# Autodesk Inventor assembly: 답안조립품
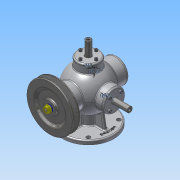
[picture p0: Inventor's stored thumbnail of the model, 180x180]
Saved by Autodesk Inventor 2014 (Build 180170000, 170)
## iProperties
Created: 2016-01
Part Number: 답안조립품
Document SubType Name: Assembly
Designer: Administrator
Mass: 3770.67 g
Surface Area: 2410.99 cm^2
Volume: 903.657 cm^3
Density: 4.17267 g/cm^3
Author: Administrator
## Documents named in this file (17)
- C:\Users\Administrator\Desktop\360108V1009\답안조립품.iam
- C:\Users\Administrator\Desktop\360108V1009\본체.ipt
- C:\Users\Administrator\Desktop\360108V1009\본체커버.ipt
- C:\Users\Administrator\Desktop\360108V1009\베어링- 6202.ipt
- C:\Users\Administrator\Desktop\360108V1009\앞커버.ipt
- C:\Users\Administrator\Desktop\360108V1009\뒤커버.ipt
- C:\Users\Administrator\Desktop\360108V1009\슬라이드 커버.ipt
- C:\Users\Administrator\Desktop\360108V1009\축.ipt
- C:\Users\Administrator\Desktop\360108V1009\오일실.ipt
- C:\Users\Administrator\Desktop\360108V1009\키-4x4.ipt
- C:\Users\Administrator\Desktop\360108V1009\V-벨트풀리.ipt
- C:\Users\Administrator\Desktop\360108V1009\와셔 8x17.ipt
- C:\Users\Administrator\Desktop\360108V1009\너트-M8x1.ipt
- C:\Users\Administrator\Desktop\360108V1009\볼트 M4x0.7.ipt
- C:\Users\Administrator\Desktop\360108V1009\슬라이드.ipt
- C:\Users\Administrator\Desktop\360108V1009\스프링1.ipt
- C:\Users\Administrator\Desktop\360108V1009\스프링2.ipt
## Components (18 placed, 2 different names)
1. V-벨트풀리:1 — 각도:2, 플러쉬:1
2. M4x0.7x12:17
3. M4x0.7x12:4
4. M4x0.7x12:5
5. M4x0.7x12:6
6. M4x0.7x12:7
7. M4x0.7x12:3
8. M4x0.7x12:8
9. M4x0.7x12:9
10. M4x0.7x12:10
11. M4x0.7x12:1
12. M4x0.7x12:11
13. M4x0.7x12:12
14. M4x0.7x12:13
15. M4x0.7x12:2
16. M4x0.7x12:14
17. M4x0.7x12:15
18. M4x0.7x12:16
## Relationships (2: Angle 1, Flush 1)
- 각도:2 [Angle]: V-벨트풀리:1
- 플러쉬:1 [Flush]: V-벨트풀리:1
